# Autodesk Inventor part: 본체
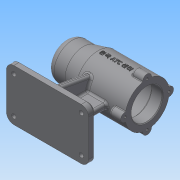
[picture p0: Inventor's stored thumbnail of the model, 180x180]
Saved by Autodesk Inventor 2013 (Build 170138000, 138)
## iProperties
Created: 2019-07
Part Number: 본체
Material: 일반
Document SubType Name: Modeling
Designer: Administrator
Density: 1 g/cm^3
Author: Administrator
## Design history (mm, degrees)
sketch "스케치1"
  geometry: L1 (56, 30)-(-11, 30); L2 (-11, 30)-(-31, 25); L3 (-31, 25)-(-56, 25); L4 (-56, 25)-(-56, 0); L5 (-56, 0)-(-50, 0); L6 (-50, 0)-(-50, 10.5); L7 (-50, 10.5)-(-47, 10.5); L8 (-47, 10.5)-(-47, 16); L9 (-47, 16)-(-43, 16); L10 (-43, 16)-(-43, 17.5); L11 (-43, 17.5)-(-25, 17.5); L12 (-25, 17.5)-(-25, 21); L13 (-25, 21)-(-13, 21); L14 (-13, 21)-(-13, 24); L15 (-13, 24)-(41, 24); L16 (41, 24)-(41, 21); L17 (41, 21)-(56, 21); L18 (56, 21)-(56, 30); L19 (-56, 0)-(56, 0); 1 further point
  constraints: 38 end point, 11 perpendicular, 6 parallel, 2 midpoint, 1 collinear, 1 horizontal
  dimensions: "d0" = 60 diameter of L1 L19; "d3" = 15 distance of L16.end L17.end; "d4" = 112 distance between parallel lines of L18 L4; "d5" = 54 distance of L14.end L15.end; "d6" = 45 distance from line of L4 L1.end; "d7" = 25 distance from line of L2.end L4; "d8" = 50 diameter of L3 L19; "d9" = 112 distance of L4.end L19.end; "d10" = 4 distance of L8.end L9.end; "d11" = 18 distance of L10.end L11.end; "d12" = 3 distance of L6.end L7.end; "d13" = 12 distance of L12.end L13.end; "d14" = 32 diameter of L9 L19; "d15" = 21 diameter of L7 L19; "d16" = 35 diameter of L11 L19; "d17" = 42 diameter of L13 L19; "d18" = 48 diameter of L15 L19; "d19" = 42 diameter of L17 L19
revolve "회전1" sketch "스케치1" stored, may be unused: angle "d20" = 90 deg
node "작업 평면1"
sketch "스케치2"
  geometry: L1 (56, -35)-(-56, -35); L2 (-56, -35)-(-56, 35); L3 (-56, 35)-(56, 35); L4 (56, 35)-(56, -35); L5 (56, -35)-(-56, 35); L6 (-56, -35)-(56, 35); 1 further point
  constraints: 12 end point, 2 midpoint, 2 parallel, 1 horizontal, 1 perpendicular
  dimensions: "d22" = 112 distance of L2.end L3.end; "d23" = 70 distance of L1.end L2.end
extrude "돌출1" join sketch "스케치2" distance "d24" = 10; taper "d25" = 0 deg
fillet "모깎기1" dims "d26" = 10, "d27" = 0.3, "d28" = 3
sketch "스케치3"
  geometry: C1 r 21 at (0, 0) reference; C2 r 6 at (0, 30); 1 further point
  constraints: 2 vertical alignment, 1 centre point, 1 other
  dimensions: "d29" = 12 diameter of C2
extrude "돌출2" join sketch "스케치3" distance "d32" = 16; taper "d33" = 0 deg
hole "구멍1" diameter "d36" = 3.242; stored, may be unused: countersink angle "d40" = 90 deg, drill point angle "d42" = 118 deg; dims "d34" = 10, "d35" = 10, "d37" = 8, "d38" = 4, "d39" = 2, "d41" = 11
sketch "스케치4"
  geometry: L1 (-19.257, -24)-(31, -24); L2 (31, -24)-(31, -70); L3 (31, -70)-(-36, -70); L4 (-36, -70)-(-19.257, -24); L5 (46, -70)-(-46, -70) reference; L6 (38, -24)-(-10, -24) reference; L7 (-56, -70)-(-46, -70) reference; L8 (-56, -80)-(-56, -70) reference; L9 (56, -70)-(56, -80) reference; 1 further point
  constraints: 8 end point, 2 collinear, 1 horizontal, 1 parallel, 1 perpendicular
  dimensions: "d46" = 110 deg angle of L7 L4; "d47" = 20 distance from line of L3.end L8; "d48" = 25 distance between parallel lines of L9 L2
extrude "돌출3" join sketch "스케치4" stored distance "d49" = 8; taper "d50" = 0 deg
sketch "스케치5"
  geometry: L1 (-22.666, 19.654)-(-70, 28); L2 (-70, 28)-(-70, -28); L3 (-70, -28)-(-22.666, -19.654); L4 (-70, -25)-(-70, -35) reference; L5 (-70, 35)-(-70, 25) reference; L6 (-70, -25)-(-70, 25) reference; L7 (-80, 35)-(-70, 35) reference; L8 (-70, -35)-(-80, -35) reference; A1 r 30 centre (0, 0) between (-29.732, -4) and (-29.732, 4) reference; A2 r 30 centre (0, 0) between (-22.666, 19.654) and (-22.666, -19.654); 1 further point
  constraints: 6 end point, 4 point on circle, 1 centre point, 1 coincident, 1 collinear, 1 vertical
  dimensions: "d51" = 100 deg angle of L3 L4; "d52" = 100 deg angle of L1 L5; "d53" = 7 distance from line of L1.end L7; "d54" = 7 distance from line of L8 L2.end
extrude "돌출4" join sketch "스케치5" stored distance "d55" = 8; taper "d56" = 0 deg
sketch "스케치6" dims "d36" = 3.242, "d38" = 4, "d39" = 2, "d41" = 11
  geometry: C1 r 3 at (-46, 25); C2 r 3 at (-46, -25); 1 further point
  constraints: 2 centre point, 1 vertical alignment
  dimensions: "d57" = 25 vertical distance of point (0, 0) C1.centre; "d58" = 50 distance of C1.centre C2.centre; "d59" = 46 horizontal distance of C1.centre point (0, 0); "d60" = 6 diameter of C1; "d61" = 6 diameter of C2
extrude "돌출5" cut sketch "스케치6" stored distance "d62" = 8; taper "d63" = 0 deg
chamfer "모따기2" distance "d68" = 3; stored, may be unused: second distance "d69" = 2, angle "d70" = 45 deg
chamfer "모따기3" distance "d71" = 1; stored, may be unused: second distance "d72" = 2, angle "d73" = 45 deg
fillet "모깎기3" dims "d74" = 3
fillet "모깎기4" dims "d75" = 1
fillet "모깎기5" dims "d76" = 3
fillet "모깎기6" dims "d77" = 3
fillet "모깎기7" dims "d78" = 3
fillet "모깎기8" dims "d79" = 3
node "작업 평면2"
sketch "스케치7"
  geometry: L1 (56, 6.771)-(56, 29.226) reference; 2 further points
  constraints: 1 horizontal alignment, 1 other
  dimensions: "d81" = 42 distance from line of L1 point (14, 0)
feature "엠보싱1" sketch "스케치7" dims "d0" = 60, "d3" = 15, "d4" = 112, "d5" = 54, "d6" = 45, "d7" = 25, "d8" = 50, "d9" = 112, "d10" = 4, "d11" = 18, "d12" = 3, "d13" = 12, "d14" = 32, "d15" = 21, "d16" = 35, "d17" = 42, "d18" = 48, "d19" = 42, "d82" = 1, "d83" = 0
node "솔리드1"
pattern_circular "원형 패턴1" dims angle "d44" = 360 deg
mirror "대칭1"
other parameters: "d80" = 30.5
